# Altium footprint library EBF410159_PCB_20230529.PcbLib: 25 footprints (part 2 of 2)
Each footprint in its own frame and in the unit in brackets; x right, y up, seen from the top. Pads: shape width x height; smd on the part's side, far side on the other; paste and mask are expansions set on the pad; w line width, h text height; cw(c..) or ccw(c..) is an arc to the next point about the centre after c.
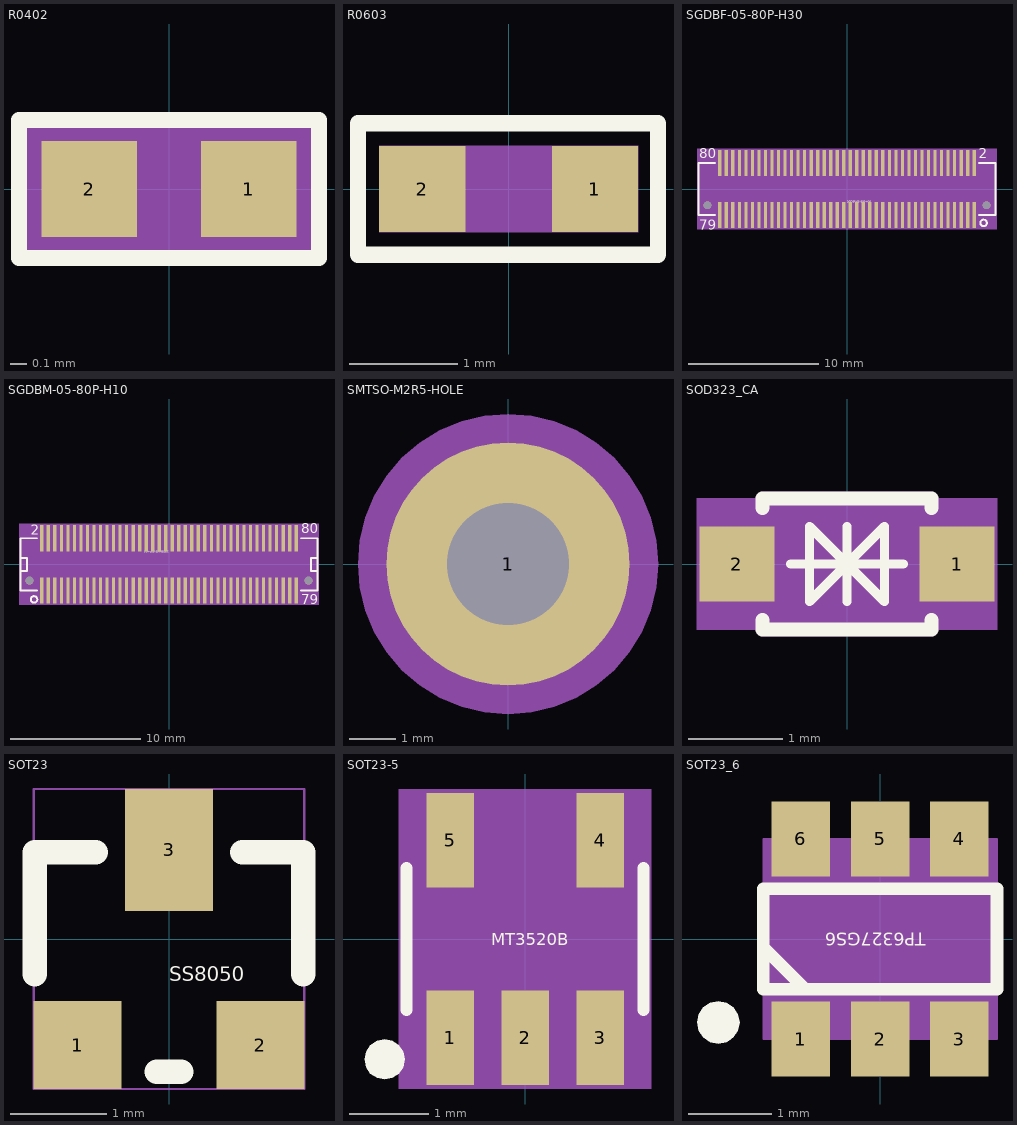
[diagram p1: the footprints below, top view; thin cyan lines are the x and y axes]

## R0402 [mm] "R0402"
pads (2):
  rect 0.599x0.599 smd: 1(0.5,0) 2(-0.5,0)
Top Overlay:
  lines w0.102: -0.94,-0.432 -0.94,0.432 0.94,0.432 0.94,-0.432 -0.94,-0.432
Top 3D Body:
  region: -0.94,-0.432 -0.94,0.432 0.94,0.432 0.94,-0.432
Top Assembly:
  dashed: 0.94,0.432 0.94,-0.432 -0.94,-0.432 -0.94,0.432
3D body: height 3.81, standoff 0, extent -0.94,-0.432 0.94,0.432

## R0603 [mil] "R0603"
pads (2):
  rect 31.5x31.5 smd: 1(31.5,0) 2(-31.5,0)
Top Overlay:
  lines w6: -55,-24 -55,24 54.5,24 54.5,-24 -55,-24
Top 3D Body:
  region: 47.24,15.75 47.24,-15.75 -47.24,-15.75 -47.24,15.75
3D body: height 150, standoff 0, extent -47.24,-15.75 47.24,15.75

## SGDBF-05-80P-H30 [mm] "SGDBF-05-80P-H30"
pads (82):
  rect 0.25x2 smd: 1(9.75,-2) 2(9.75,2) 3(9.25,-2) 4(9.25,2) 5(8.75,-2) 6(8.75,2) 7(8.25,-2) 8(8.25,2) 9(7.75,-2) 10(7.75,2) 11(7.25,-2) 12(7.25,2) 13(6.75,-2) 14(6.75,2) 15(6.25,-2) 16(6.25,2) 17(5.75,-2) 18(5.75,2) 19(5.25,-2) 20(5.25,2) 21(4.75,-2) 22(4.75,2) 23(4.25,-2) 24(4.25,2) 25(3.75,-2) 26(3.75,2) 27(3.25,-2) 28(3.25,2) 29(2.75,-2) 30(2.75,2) 31(2.25,-2) 32(2.25,2) 33(1.75,-2) 34(1.75,2) 35(1.25,-2) 36(1.25,2) 37(0.75,-2) 38(0.75,2) 39(0.25,-2) 40(0.25,2) 41(-0.25,-2) 42(-0.25,2) 43(-0.75,-2) 44(-0.75,2) 45(-1.25,-2) 46(-1.25,2) 47(-1.75,-2) 48(-1.75,2) 49(-2.25,-2) 50(-2.25,2) 51(-2.75,-2) 52(-2.75,2) 53(-3.25,-2) 54(-3.25,2) 55(-3.75,-2) 56(-3.75,2) 57(-4.25,-2) 58(-4.25,2) 59(-4.75,-2) 60(-4.75,2) 61(-5.25,-2) 62(-5.25,2) 63(-5.75,-2) 64(-5.75,2) 65(-6.25,-2) 66(-6.25,2) 67(-6.75,-2) 68(-6.75,2) 69(-7.25,-2) 70(-7.25,2) 71(-7.75,-2) 72(-7.75,2) 73(-8.25,-2) 74(-8.25,2) 75(-8.75,-2) 76(-8.75,2) 77(-9.25,-2) 78(-9.25,2) 79(-9.75,-2) 80(-9.75,2)
  round 0.6 hole 0.6 unplated: ""(-10.7,-1.25) ""(10.7,-1.25)
Top Overlay:
  circle w0.15: c10.475,-2.603 r0.25
  lines w0.15: -10.1,-2 -11.4,-2 -11.4,2 -10.1,2 ; 10.1,-2 11.4,-2 11.4,2 10.1,2
  text "SGDBF-05-80P-H30" at 0,-1.052 h0.15
  text "80" at -11.318,2.35 h0.76
  text "2" at 10.094,2.35 h0.76
  text "79" at -11.318,-3.111 h0.76
Top 3D Body:
  region: 11.5,-3.1 11.5,3.1 -11.5,3.1 -11.5,-3.1
Mechanical 14:
  text "51" at -2.75,-2.508 h0.64
  text "53" at -3.25,-2.508 h0.64
  text "55" at -3.75,-2.508 h0.64
  text "57" at -4.25,-2.508 h0.64
  text "59" at -4.75,-2.508 h0.64
  text "61" at -5.25,-2.508 h0.64
  text "63" at -5.75,-2.508 h0.64
  text "65" at -6.25,-2.508 h0.64
  text "68" at -6.75,1.492 h0.64
  text "69" at -7.25,-2.508 h0.64
  text "70" at -7.25,1.492 h0.64
  text "71" at -7.75,-2.508 h0.64
  text "72" at -7.75,1.492 h0.64
  text "74" at -8.25,1.492 h0.64
  text "75" at -8.75,-2.508 h0.64
  text "77" at -9.25,-2.508 h0.64
  text "79" at -9.75,-2.508 h0.64
  text "76" at -8.75,1.492 h0.64
  text "66" at -6.25,1.492 h0.64
  text "56" at -3.75,1.492 h0.64
  text "50" at -2.25,1.492 h0.64
  text "40" at 0.25,1.492 h0.64
  text "32" at 2.25,1.492 h0.64
  text "26" at 3.75,1.492 h0.64
  text "20" at 5.25,1.492 h0.64
  text "16" at 6.25,1.492 h0.64
  text "10" at 7.75,1.492 h0.64
  text "8" at 8.25,1.746 h0.64
  text "73" at -8.25,-2.508 h0.64
  text "67" at -6.75,-2.508 h0.64
  text "49" at -2.25,-2.508 h0.64
  text "31" at 2.25,-2.508 h0.64
  text "23" at 4.25,-2.508 h0.64
  text "9" at 7.75,-2.254 h0.64
  text "7" at 8.25,-2.254 h0.64
  text "48" at -1.75,1.492 h0.64
  text "44" at -0.75,1.492 h0.64
  text "54" at -3.25,1.492 h0.64
  text "33" at 1.75,-2.508 h0.64
  text "39" at 0.25,-2.508 h0.64
  text "35" at 1.25,-2.508 h0.64
  text "41" at -0.25,-2.508 h0.64
  text "45" at -1.25,-2.508 h0.64
  text "43" at -0.75,-2.508 h0.64
  text "37" at 0.75,-2.508 h0.64
  text "60" at -4.75,1.492 h0.64
  text "58" at -4.25,1.492 h0.64
  text "64" at -5.75,1.492 h0.64
  text "62" at -5.25,1.492 h0.64
  text "47" at -1.75,-2.508 h0.64
  text "36" at 1.25,1.492 h0.64
  text "38" at 0.75,1.492 h0.64
  text "27" at 3.25,-2.508 h0.64
  text "34" at 1.75,1.492 h0.64
  text "22" at 4.75,1.492 h0.64
  text "24" at 4.25,1.492 h0.64
  text "21" at 4.75,-2.508 h0.64
  text "19" at 5.25,-2.508 h0.64
  text "17" at 5.75,-2.508 h0.64
  text "15" at 6.25,-2.508 h0.64
  text "14" at 6.75,1.492 h0.64
  text "12" at 7.25,1.492 h0.64
  text "13" at 6.75,-2.508 h0.64
  text "11" at 7.25,-2.508 h0.64
  text "52" at -2.75,1.492 h0.64
  text "80" at -9.75,1.492 h0.64
  text "25" at 3.75,-2.508 h0.64
  text "46" at -1.25,1.492 h0.64
  text "42" at -0.25,1.492 h0.64
  text "6" at 8.75,1.746 h0.64
  text "4" at 9.25,1.746 h0.64
  text "2" at 9.75,1.746 h0.64
  text "5" at 8.75,-2.254 h0.64
  text "3" at 9.25,-2.254 h0.64
  text "1" at 9.75,-2.254 h0.64
  text "29" at 2.75,-2.508 h0.64
  text "18" at 5.75,1.492 h0.64
  text "78" at -9.25,1.492 h0.64
  text "30" at 2.75,1.492 h0.64
  text "28" at 3.25,1.492 h0.64
Top Assembly:
  lines w0.15: -11.4,-2 11.4,-2 11.4,2 -11.4,2 -11.4,-2
3D body: height 3.81, standoff 0, extent -11.5,-3.1 11.5,3.1

## SGDBM-05-80P-H10 [mm] "SGDBM-05-80P-H10"
pads (82):
  rect 0.25x2 smd: 1(-9.75,-2) 2(-9.75,2) 3(-9.25,-2) 4(-9.25,2) 5(-8.75,-2) 6(-8.75,2) 7(-8.25,-2) 8(-8.25,2) 9(-7.75,-2) 10(-7.75,2) 11(-7.25,-2) 12(-7.25,2) 13(-6.75,-2) 14(-6.75,2) 15(-6.25,-2) 16(-6.25,2) 17(-5.75,-2) 18(-5.75,2) 19(-5.25,-2) 20(-5.25,2) 21(-4.75,-2) 22(-4.75,2) 23(-4.25,-2) 24(-4.25,2) 25(-3.75,-2) 26(-3.75,2) 27(-3.25,-2) 28(-3.25,2) 29(-2.75,-2) 30(-2.75,2) 31(-2.25,-2) 32(-2.25,2) 33(-1.75,-2) 34(-1.75,2) 35(-1.25,-2) 36(-1.25,2) 37(-0.75,-2) 38(-0.75,2) 39(-0.25,-2) 40(-0.25,2) 41(0.25,-2) 42(0.25,2) 43(0.75,-2) 44(0.75,2) 45(1.25,-2) 46(1.25,2) 47(1.75,-2) 48(1.75,2) 49(2.25,-2) 50(2.25,2) 51(2.75,-2) 52(2.75,2) 53(3.25,-2) 54(3.25,2) 55(3.75,-2) 56(3.75,2) 57(4.25,-2) 58(4.25,2) 59(4.75,-2) 60(4.75,2) 61(5.25,-2) 62(5.25,2) 63(5.75,-2) 64(5.75,2) 65(6.25,-2) 66(6.25,2) 67(6.75,-2) 68(6.75,2) 69(7.25,-2) 70(7.25,2) 71(7.75,-2) 72(7.75,2) 73(8.25,-2) 74(8.25,2) 75(8.75,-2) 76(8.75,2) 77(9.25,-2) 78(9.25,2) 79(9.75,-2) 80(9.75,2)
  round 0.6 hole 0.6 unplated: ""(-10.7,-1.25) ""(10.7,-1.25)
Top Overlay:
  circle w0.15: c-10.348,-2.688 r0.25
  lines w0.15: -11.4,0 -11.4,-0.5 -10.9,-0.5 -10.9,0.5 -11.4,0.5 ; -10.1,-2 -11.4,-2 -11.4,2 -10.1,2 ; 10.1,-2 11.4,-2 11.4,2 10.1,2 ; 11.4,0 11.4,-0.5 10.9,-0.5 10.9,0.5 11.4,0.5
  text "SGDBM-05-80P-H10" at 0,1.052 h0.15
  text "2" at -10.602,2.265 h0.76
  text "79" at 10.15,-3.069 h0.76
  text "80" at 10.15,2.392 h0.76
Top 3D Body:
  region: -11.5,3.1 -11.5,-3.1 11.5,-3.1 11.5,3.1
Mechanical 14:
  text "64" at 5.75,2.508 h0.64
  text "62" at 5.25,2.508 h0.64
  text "60" at 4.75,2.508 h0.64
  text "58" at 4.25,2.508 h0.64
  text "56" at 3.75,2.508 h0.64
  text "8" at -8.25,2.254 h0.64
  text "80" at 9.75,2.508 h0.64
  text "66" at 6.25,2.508 h0.64
  text "54" at 3.25,2.508 h0.64
  text "36" at -1.25,2.508 h0.64
  text "26" at -3.75,2.508 h0.64
  text "24" at -4.25,2.508 h0.64
  text "18" at -5.75,2.508 h0.64
  text "2" at -9.75,2.254 h0.64
  text "79" at 9.75,-1.492 h0.64
  text "65" at 6.25,-1.492 h0.64
  text "55" at 3.75,-1.492 h0.64
  text "49" at 2.25,-1.492 h0.64
  text "39" at -0.25,-1.492 h0.64
  text "29" at -2.75,-1.492 h0.64
  text "23" at -4.25,-1.492 h0.64
  text "13" at -6.75,-1.492 h0.64
  text "3" at -9.25,-1.746 h0.64
  text "1" at -9.75,-1.746 h0.64
  text "10" at -7.75,2.508 h0.64
  text "16" at -6.25,2.508 h0.64
  text "4" at -9.25,2.254 h0.64
  text "6" at -8.75,2.254 h0.64
  text "5" at -8.75,-1.746 h0.64
  text "14" at -6.75,2.508 h0.64
  text "7" at -8.25,-1.746 h0.64
  text "12" at -7.25,2.508 h0.64
  text "11" at -7.25,-1.492 h0.64
  text "9" at -7.75,-1.746 h0.64
  text "37" at -0.75,-1.492 h0.64
  text "35" at -1.25,-1.492 h0.64
  text "33" at -1.75,-1.492 h0.64
  text "34" at -1.75,2.508 h0.64
  text "50" at 2.25,2.508 h0.64
  text "52" at 2.75,2.508 h0.64
  text "48" at 1.75,2.508 h0.64
  text "46" at 1.25,2.508 h0.64
  text "44" at 0.75,2.508 h0.64
  text "42" at 0.25,2.508 h0.64
  text "40" at -0.25,2.508 h0.64
  text "38" at -0.75,2.508 h0.64
  text "32" at -2.25,2.508 h0.64
  text "28" at -3.25,2.508 h0.64
  text "30" at -2.75,2.508 h0.64
  text "27" at -3.25,-1.492 h0.64
  text "31" at -2.25,-1.492 h0.64
  text "21" at -4.75,-1.492 h0.64
  text "19" at -5.25,-1.492 h0.64
  text "17" at -5.75,-1.492 h0.64
  text "15" at -6.25,-1.492 h0.64
  text "77" at 9.25,-1.492 h0.64
  text "75" at 8.75,-1.492 h0.64
  text "78" at 9.25,2.508 h0.64
  text "76" at 8.75,2.508 h0.64
  text "73" at 8.25,-1.492 h0.64
  text "71" at 7.75,-1.492 h0.64
  text "69" at 7.25,-1.492 h0.64
  text "67" at 6.75,-1.492 h0.64
  text "74" at 8.25,2.508 h0.64
  text "72" at 7.75,2.508 h0.64
  text "70" at 7.25,2.508 h0.64
  text "68" at 6.75,2.508 h0.64
  text "53" at 3.25,-1.492 h0.64
  text "51" at 2.75,-1.492 h0.64
  text "63" at 5.75,-1.492 h0.64
  text "61" at 5.25,-1.492 h0.64
  text "59" at 4.75,-1.492 h0.64
  text "57" at 4.25,-1.492 h0.64
  text "20" at -5.25,2.508 h0.64
  text "47" at 1.75,-1.492 h0.64
  text "22" at -4.75,2.508 h0.64
  text "45" at 1.25,-1.492 h0.64
  text "43" at 0.75,-1.492 h0.64
  text "41" at 0.25,-1.492 h0.64
  text "25" at -3.75,-1.492 h0.64
Top Assembly:
  lines w0.15: -11.4,-2 11.4,-2 11.4,2 -11.4,2 -11.4,-2
3D body: height 3.81, standoff 0, extent -11.5,-3.1 11.5,3.1

## SMTSO-M2R5-HOLE [mm] "SMTSO-M2R5-HOLE"
pads (1):
  round 5.2 / inner round 5.2 / far side round 6.2 hole 2.6: 1(0,0)
Top Overlay:
  text "PTH_M2.5" at 0.488,0.076 h0.15
Top 3D Body:
  region: -3.21,0 -3.17,-0.502 -3.053,-0.992 -2.86,-1.457 -2.597,-1.887 -2.27,-2.27 -1.887,-2.597 -1.457,-2.86 -0.992,-3.053 -0.502,-3.17 0,-3.21 0.502,-3.17 0.992,-3.053 1.457,-2.86 1.6,-2.772 1.887,-2.597 2.27,-2.27 2.597,-1.887 2.86,-1.457 3.053,-0.992 3.17,-0.502 3.21,0 3.17,0.502 3.053,0.992 2.86,1.457 2.597,1.887 2.27,2.27 1.887,2.597 1.6,2.772 1.457,2.86 0.992,3.053 0.502,3.17 0,3.21 -0.502,3.17 -0.992,3.053 -1.457,2.86 -1.887,2.597 -2.27,2.27 -2.597,1.887 -2.86,1.457 -3.053,0.992 -3.17,0.502
Mechanical 14:
  text "1" at 0.254,0 h0.64
Top Assembly:
  dashed: -3.11,0 -3.071,-0.486 -2.957,-0.961 -2.771,-1.412 -2.516,-1.828 -2.199,-2.199 -1.828,-2.516 -1.412,-2.771 -0.961,-2.957 -0.486,-3.071 0,-3.11 0.486,-3.071 0.961,-2.957 1.412,-2.771 1.551,-2.686 1.828,-2.516 2.199,-2.199 2.516,-1.828 2.771,-1.412 2.957,-0.961 3.071,-0.486 3.11,0 3.071,0.486 2.957,0.961 2.771,1.412 2.516,1.828 2.199,2.199 1.828,2.516 1.551,2.686 1.412,2.771 0.961,2.957 0.486,3.071 0,3.11 -0.486,3.071 -0.961,2.957 -1.412,2.771 -1.828,2.516 -2.199,2.199 -2.516,1.828 -2.771,1.412 -2.957,0.961 -3.071,0.486
3D body: height 3.81, standoff 0, extent -3.21,-3.21 3.21,3.21

## SOD323_CA [mil] "SOD323_CA"
pads (2):
  rect 31.5x31.5 smd: 1(46.26,0) 2(-46.26,0)
Top Overlay:
  lines w3.94: -23.62,0 23.62,0 ; 0,-15.75 0,15.75 ; 0,0 -15.75,15.75 -15.75,-15.75 0,0 ; 0,0 15.75,-15.75 15.75,15.75 0,0
  lines w5.91: -35.43,-23.62 -35.43,-27.56 35.43,-27.56 35.43,-23.62 ; -35.43,23.62 -35.43,27.56 35.43,27.56 35.43,23.62
Top 3D Body:
  region: 62.99,-27.56 62.99,27.56 -62.99,27.56 -62.99,-27.56
Mechanical 14:
  text "1" at 36.26,0 h25
Top Assembly:
  lines w5.91: -35.43,-27.56 -35.43,27.56 35.43,27.56 35.43,-27.56 -35.43,-27.56
3D body: height 150, standoff 0, extent -62.99,-27.56 62.99,27.56

## SOT23 [mil] "SOT23"
pads (3):
  rect 36x36 smd: 1(-37.5,-43.5) 2(37.5,-43.5)
  rect 36x50 smd: 3(0,36.5)
Top Overlay:
  lines w10: -55,-14.5 -55,35.5 -30,35.5 ; -5,-54.5 5,-54.5 ; 30,35.5 55,35.5 55,-14.5
  text "SS8050" at 0.01,-17.4 h6
Top 3D Body:
  lines w1: -55.5,-61.5 55.5,-61.5 55.5,61.5 -55.5,61.5 -55.5,-61.5

## SOT23-5 [mm] "SOT23-5"
pads (5):
  rect 0.599x1.199 smd: 1(-0.95,-1.25) 2(0,-1.25) 3(0.95,-1.25) 4(0.95,1.25) 5(-0.95,1.25)
Top Overlay:
  dashed: -1.523,-1.524 -1.543,-1.426 -1.598,-1.344 -1.68,-1.289 -1.778,-1.269 -1.876,-1.289 -1.903,-1.307 -1.958,-1.344 -2.013,-1.426 -2.033,-1.524 -2.013,-1.622 -1.958,-1.704 -1.903,-1.741 -1.876,-1.759 -1.778,-1.779 -1.68,-1.759 -1.598,-1.704 -1.543,-1.622
  lines w0.15: -1.5,-0.9 -1.5,0.9 ; 1.5,-0.9 1.5,0.9
  text "MT3520B" at -0.427,-0.076 h0.15
Top 3D Body:
  region: -1.6,1.9 -1.6,-1.9 1.6,-1.9 1.6,1.9
Mechanical 14:
  text "3" at 0.91,-1.25 h0.1
  text "5" at -0.99,1.25 h0.1
  text "1" at -0.99,-1.25 h0.1
  text "4" at 0.91,1.25 h0.1
  text "2" at -0.04,-1.25 h0.1
Top Assembly:
  lines w0.15: -1.5,-0.85 -1.5,0.85 1.5,0.85 1.5,-0.85 -1.5,-0.85
3D body: height 3.81, standoff 0, extent -1.6,-1.9 1.6,1.9

## SOT23_6 [mm] "SOT23_6"
pads (6):
  rect 0.7x0.9 smd: 1(-0.95,-1.2) 2(0,-1.2) 3(0.95,-1.2) 4(0.95,1.2) 5(0,1.2) 6(-0.95,1.2)
Top Overlay:
  dashed: -2.195,-1 -2.175,-1.098 -2.12,-1.18 -2.038,-1.235 -1.94,-1.255 -1.843,-1.235 -1.815,-1.217 -1.76,-1.18 -1.705,-1.098 -1.685,-1 -1.705,-0.902 -1.76,-0.82 -1.815,-0.783 -1.843,-0.765 -1.94,-0.745 -2.038,-0.765 -2.12,-0.82 -2.175,-0.902
  lines w0.15: -1.4,-0.1 -0.9,-0.6 ; -1.4,-0.6 1.4,-0.6 1.4,0.6 -1.4,0.6 -1.4,-0.6
  text "TP6327GS6" at 0.549,0.076 h0.15
Top 3D Body:
  region: -1.4,-1.2 1.4,-1.2 1.4,1.2 -1.4,1.2
Mechanical 14:
  text "2" at 0.254,-1.2 h0.64
  text "1" at -0.696,-1.2 h0.64
Top Assembly:
  lines w0.025: -1.4,-1.2 -1.4,1.2 1.4,1.2 1.4,-1.2 -1.4,-1.2
3D body: height 3.81, standoff 0, extent -1.4,-1.2 1.4,1.2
